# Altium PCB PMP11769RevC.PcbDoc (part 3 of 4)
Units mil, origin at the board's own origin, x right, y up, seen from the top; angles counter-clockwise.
Board outline 7800 x 8510 mil, 4 copper layers (Top, Inner Top, Inner Bottom, Bottom), stack 33.235 mil thick; 451 components, 226 nets, 1199 pads, 1742 vias.
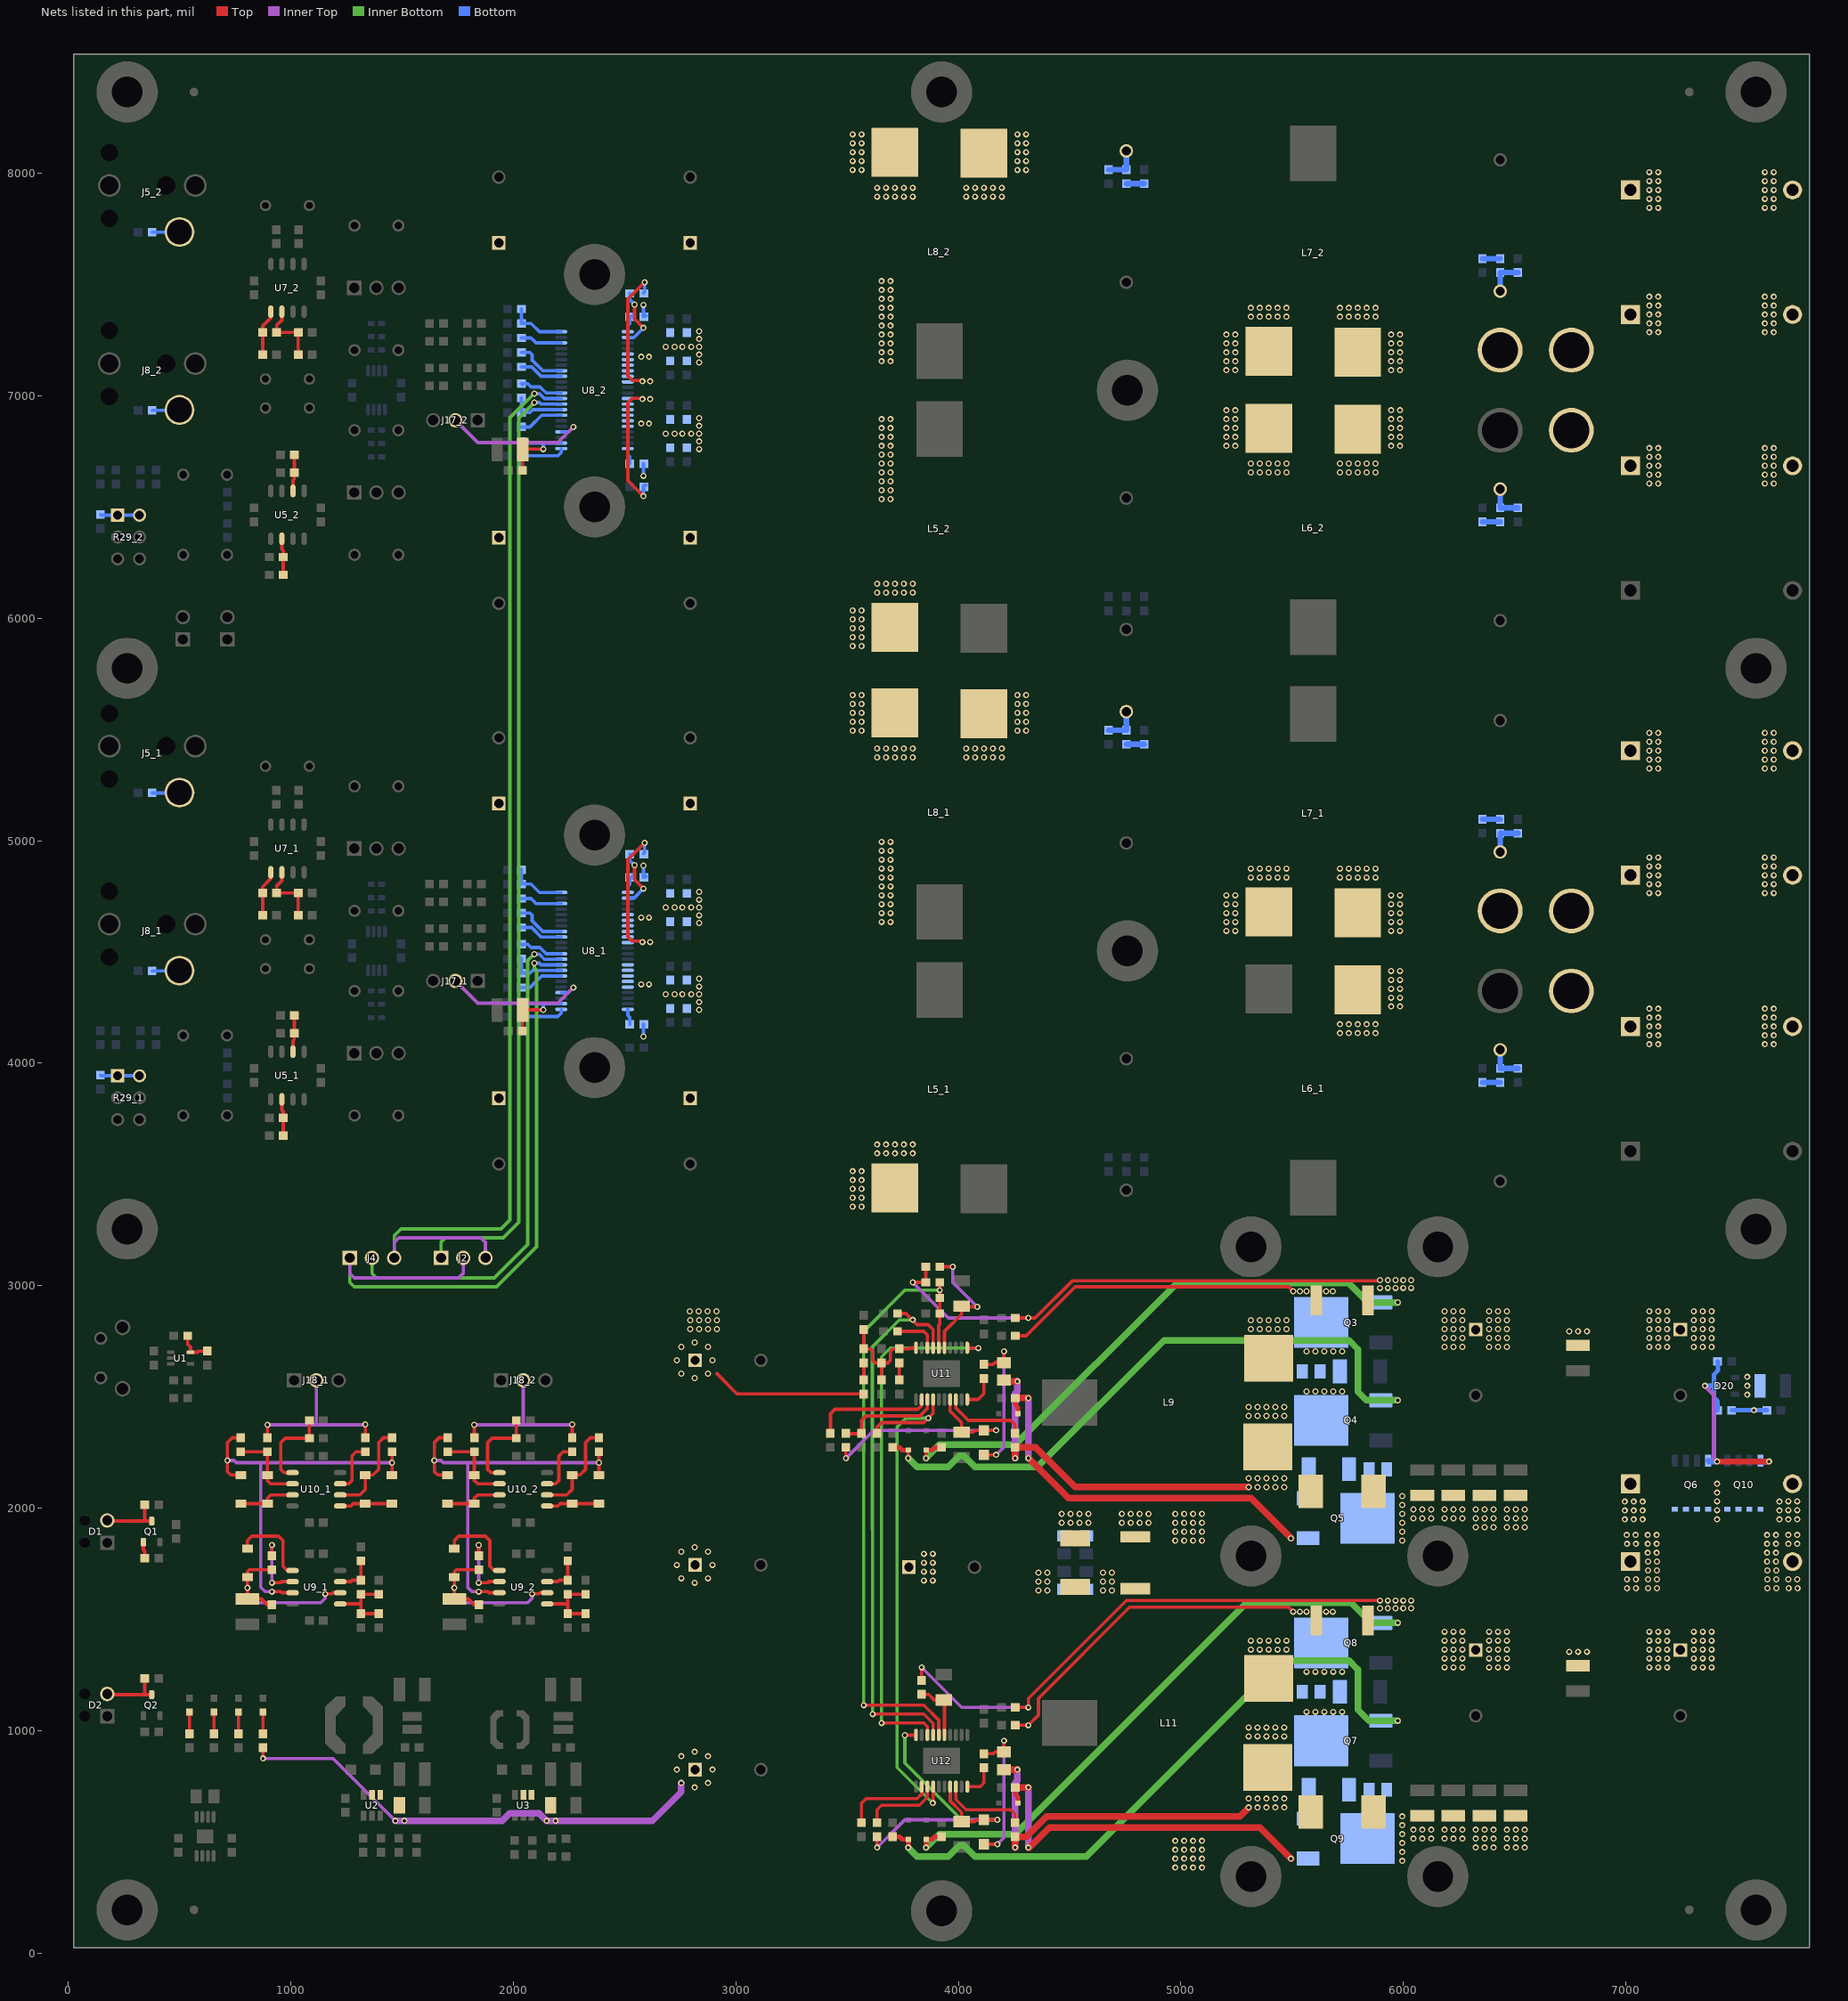
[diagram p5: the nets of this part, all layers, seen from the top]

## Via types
v1: diameter 28, hole 15, Top to Bottom, 1742 vias

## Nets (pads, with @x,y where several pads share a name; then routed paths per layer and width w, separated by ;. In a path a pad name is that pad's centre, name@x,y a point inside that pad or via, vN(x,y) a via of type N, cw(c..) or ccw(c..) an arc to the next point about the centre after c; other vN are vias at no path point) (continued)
NetC54_2_2: C54_2.2 L6_2.2 U8_2.35 | length 576.3
  Top w15: v1(2585,6548.7) 2515,6618.7 2515,6968.7 2535,6988.7 v1@2585,6988.7
  Bottom w15: v1(2585,6548.7) 2585,6593.5 C54_2.2@2586.5,6595 ; C54_2.2@2595,6600.2 C54_2.2@2596.5,6598.7
  other v1: 3655,6535 3695,6535 3655,6575 3695,6575 3655,6615 3695,6615 3655,6655 3695,6655 5315,6655 5355,6655 5395,6655 5435,6655 5475,6655 3655,6695 3695,6695 5315,6695 5355,6695 5395,6695 5435,6695 5475,6695 3655,6735 3695,6735 3655,6775 3695,6775 5205,6775 5245,6775 3655,6815 3695,6815 5205,6815 5245,6815 3655,6855 3695,6855 5205,6855 5245,6855 3655,6895 3695,6895 5205,6895 5245,6895 5205,6935 5245,6935 2580,6985 2615,6985
NetC55_1_1: C55_1.1 U8_1.44 | length 71.2
  Bottom w15: U8_1.44@2514.61,4242.5 2514.61,4215.39 2523.5,4206.5 C55_1.1@2523.5,4175
NetC55_1_2: C55_1.2 L5_1.1 U8_1.39 U8_1.40 | length 53.5
  Bottom w15: v1(2585,4120) C55_1.2@2585,4173.5
  other v1: 3525,3355 3565,3355 3525,3395 3565,3395 3525,3435 3565,3435 3525,3475 3565,3475 3525,3515 3565,3515 3635,3595 3675,3595 3715,3595 3755,3595 3795,3595 3635,3635 3675,3635 3715,3635 3755,3635 3795,3635 2575,4355 2610,4355
NetC55_2_1: C55_2.1 U8_2.44 | length 71.2
  Bottom w15: U8_2.44@2514.61,6762.5 2514.61,6735.39 2523.5,6726.5 C55_2.1@2523.5,6695
NetC55_2_2: C55_2.2 L5_2.1 U8_2.39 U8_2.40 | length 53.5
  Bottom w15: v1(2585,6640) C55_2.2@2585,6693.5
  other v1: 3525,5875 3565,5875 3525,5915 3565,5915 3525,5955 3565,5955 3525,5995 3565,5995 3525,6035 3565,6035 3635,6115 3675,6115 3715,6115 3755,6115 3795,6115 3635,6155 3675,6155 3715,6155 3755,6155 3795,6155 2575,6875 2610,6875
NetC58_1_1: C58_1.1 U8_1.11 | length 203.6
  Bottom w15: C58_1.1@2041.5,4530 C58_1.1@2036.5,4535 2065.02,4535 2080.02,4520 2120,4520 2147.5,4492.5 U8_1.11@2215.39,4492.5
NetC58_2_1: C58_2.1 U8_2.11 | length 203.6
  Bottom w15: C58_2.1@2041.5,7050 C58_2.1@2036.5,7055 2065.02,7055 2080.02,7040 2120,7040 2147.5,7012.5 U8_2.11@2215.39,7012.5
NetC59_1_1: C59_1.1 U8_1.14 | length 196.9
  Bottom w15: C59_1.1@2036.5,4610 2082.65,4610 2125.15,4567.5 U8_1.14@2215.39,4567.5 U8_1.14@2215.39,4567.87
NetC59_2_1: C59_2.1 U8_2.14 | length 196.9
  Bottom w15: C59_2.1@2036.5,7130 2082.65,7130 2125.15,7087.5 U8_2.14@2215.39,7087.5 U8_2.14@2215.39,7087.87
NetC60_1_2: C60_1.2 R46_1.1 U8_1.1 | length 271.1
  Bottom w15: R46_1.1@2036.5,4145 C60_1.2@2036.5,4210 C60_1.2@2046.5,4210 ; C60_1.2@2046.5,4213.7 C60_1.2@2046.5,4210 ; U8_1.1@2215.39,4242.5 2215.39,4225.39 2200,4210 C60_1.2@2046.5,4210
NetC60_2_2: C60_2.2 R46_2.1 U8_2.1 | length 271.1
  Bottom w15: R46_2.1@2036.5,6665 C60_2.2@2036.5,6730 C60_2.2@2046.5,6730 ; C60_2.2@2046.5,6733.7 C60_2.2@2046.5,6730 ; U8_2.1@2215.39,6762.5 2215.39,6745.39 2200,6730 C60_2.2@2046.5,6730
NetC61_1_1: C61_1.1 C62_1.1 C63_1.1 J11_1.1 J12_1.1 J12_1.2 L6_1.1 | length 163.8
  Bottom w25: C62_1.1@6435,4060.28 C61_1.1@6435,3976.5 C63_1.1@6515,3976.5
  other v1: 7105,4085 7145,4085 7625,4085 7665,4085 7105,4125 7145,4125 7625,4125 7665,4125 5715,4135 5755,4135 5795,4135 5835,4135 5875,4135 7105,4165 7145,4165 7625,4165 7665,4165 5715,4175 5755,4175 5795,4175 5835,4175 5875,4175 7105,4205 7145,4205 7625,4205 7665,4205 7105,4245 7145,4245 7625,4245 7665,4245 5945,4255 5985,4255 5945,4295 5985,4295 5945,4335 5985,4335 5945,4375 5985,4375 5945,4415 5985,4415
NetC61_1_2: C61_1.2 R47_1.2 | length 80
  Bottom w25: R47_1.2@6355,3913.5 C61_1.2@6435,3913.5
NetC61_2_1: C61_2.1 C62_2.1 C63_2.1 J11_2.1 J12_2.1 J12_2.2 L6_2.1 | length 163.8
  Bottom w25: C62_2.1@6435,6580.28 C61_2.1@6435,6496.5 C63_2.1@6515,6496.5
  other v1: 7105,6605 7145,6605 7625,6605 7665,6605 7105,6645 7145,6645 7625,6645 7665,6645 5715,6655 5755,6655 5795,6655 5835,6655 5875,6655 7105,6685 7145,6685 7625,6685 7665,6685 5715,6695 5755,6695 5795,6695 5835,6695 5875,6695 7105,6725 7145,6725 7625,6725 7665,6725 7105,6765 7145,6765 7625,6765 7665,6765 5945,6775 5985,6775 5945,6815 5985,6815 5945,6855 5985,6855 5945,6895 5985,6895 5945,6935 5985,6935
NetC61_2_2: C61_2.2 R47_2.2 | length 80
  Bottom w25: R47_2.2@6355,6433.5 C61_2.2@6435,6433.5
NetC64_1_1: C64_1.1 L7_1.1 U8_1.32 | length 581.2
  Top w15: v1@2585,4548.7 2535,4548.7 2515,4568.7 2515,4915 v1(2590,4990)
  Bottom w15: C64_1.1@2585,4941.5 2590,4946.5 v1(2590,4990)
  other v1: 2580,4545 2615,4545 5205,4595 5245,4595 3655,4635 3695,4635 5205,4635 5245,4635 3655,4675 3695,4675 5205,4675 5245,4675 3655,4715 3695,4715 5205,4715 5245,4715 3655,4755 3695,4755 5205,4755 5245,4755 3655,4795 3695,4795 3655,4835 3695,4835 5315,4835 5355,4835 5395,4835 5435,4835 5475,4835 3655,4875 3695,4875 5315,4875 5355,4875 5395,4875 5435,4875 5475,4875 3655,4915 3695,4915 3655,4955 3695,4955 3655,4995 3695,4995
NetC64_1_2: C64_1.2 U8_1.24 | length 268.5
  Top w15: v1(2545,4890) 2545,4825 v1(2585,4785)
  Bottom w15: U8_1.24@2514.61,4742.5 2542.5,4742.5 v1(2585,4785) ; C64_1.2@2523.5,4940 2523.5,4911.5 v1(2545,4890)
NetC64_2_1: C64_2.1 L7_2.1 U8_2.32 | length 581.2
  Top w15: v1@2585,7068.7 2535,7068.7 2515,7088.7 2515,7435 v1(2590,7510)
  Bottom w15: C64_2.1@2585,7461.5 2590,7466.5 v1(2590,7510)
  other v1: 2580,7065 2615,7065 5205,7115 5245,7115 3655,7155 3695,7155 5205,7155 5245,7155 3655,7195 3695,7195 5205,7195 5245,7195 3655,7235 3695,7235 5205,7235 5245,7235 3655,7275 3695,7275 5205,7275 5245,7275 3655,7315 3695,7315 3655,7355 3695,7355 5315,7355 5355,7355 5395,7355 5435,7355 5475,7355 3655,7395 3695,7395 5315,7395 5355,7395 5395,7395 5435,7395 5475,7395 3655,7435 3695,7435 3655,7475 3695,7475 3655,7515 3695,7515
NetC64_2_2: C64_2.2 U8_2.24 | length 268.5
  Top w15: v1(2545,7410) 2545,7345 v1(2585,7305)
  Bottom w15: U8_2.24@2514.61,7262.5 2542.5,7262.5 v1(2585,7305) ; C64_2.2@2523.5,7460 2523.5,7431.5 v1(2545,7410)
NetC65_1_1: C65_1.1 L8_1.2 U8_1.27 U8_1.28 | length 56.4
  Bottom w15: v1(2585,4888.7) 2585,4836.5 C65_1.1@2586.5,4835 ; C65_1.1@2595,4840.2 C65_1.1@2596.5,4838.7
  other v1: 2575,4655 2610,4655 3635,5375 3675,5375 3715,5375 3755,5375 3795,5375 3635,5415 3675,5415 3715,5415 3755,5415 3795,5415 3525,5495 3565,5495 3525,5535 3565,5535 3525,5575 3565,5575 3525,5615 3565,5615 3525,5655 3565,5655
NetC65_1_2: C65_1.2 U8_1.23 | length 83.8
  Bottom w15: U8_1.23@2514.61,4767.5 2514.61,4794.61 2523.5,4803.5 C65_1.2@2523.5,4835 ; C65_1.2@2524.61,4829.8 C65_1.2@2533.5,4838.7
NetC65_2_1: C65_2.1 L8_2.2 U8_2.27 U8_2.28 | length 56.4
  Bottom w15: v1(2585,7408.7) 2585,7356.5 C65_2.1@2586.5,7355 ; C65_2.1@2595,7360.2 C65_2.1@2596.5,7358.7
  other v1: 2575,7175 2610,7175 3635,7895 3675,7895 3715,7895 3755,7895 3795,7895 3635,7935 3675,7935 3715,7935 3755,7935 3795,7935 3525,8015 3565,8015 3525,8055 3565,8055 3525,8095 3565,8095 3525,8135 3565,8135 3525,8175 3565,8175
NetC65_2_2: C65_2.2 U8_2.23 | length 83.8
  Bottom w15: U8_2.23@2514.61,7287.5 2514.61,7314.61 2523.5,7323.5 C65_2.2@2523.5,7355 ; C65_2.2@2524.61,7349.8 C65_2.2@2533.5,7358.7
NetC66_1_2: C66_1.2 C67_1.1 R48_1.1 U8_1.2 | length 396.8
  Top w15: R48_1.1@2041.5,4145 2042.09,4145.59 C67_1.1@2042.09,4238.54 2043.54,4240 v1(2135,4240)
  Bottom w15: C66_1.2@2036.5,4275 2066.02,4275 2073.52,4267.5 2135,4267.5 ; v1(2135,4240) 2135,4267.5 ; U8_1.2@2215.39,4267.5 2135,4267.5
NetC66_2_2: C66_2.2 C67_2.1 R48_2.1 U8_2.2 | length 396.8
  Top w15: R48_2.1@2041.5,6665 2042.09,6665.59 C67_2.1@2042.09,6758.54 2043.54,6760 v1(2135,6760)
  Bottom w15: C66_2.2@2036.5,6795 2066.02,6795 2073.52,6787.5 2135,6787.5 ; v1(2135,6760) 2135,6787.5 ; U8_2.2@2215.39,6787.5 2135,6787.5
NetC68_1_1: C68_1.1 C69_1.1 C70_1.1 J13_1.1 J13_1.2 J14_1.1 L7_1.2 | length 163.8
  Bottom w25: C69_1.1@6435,4949.72 C68_1.1@6435,5033.5 C70_1.1@6515,5033.5
  other v1: 5945,4595 5985,4595 5945,4635 5985,4635 5945,4675 5985,4675 5945,4715 5985,4715 5945,4755 5985,4755 7105,4765 7145,4765 7625,4765 7665,4765 7105,4805 7145,4805 7625,4805 7665,4805 5715,4835 5755,4835 5795,4835 5835,4835 5875,4835 7105,4845 7145,4845 7625,4845 7665,4845 5715,4875 5755,4875 5795,4875 5835,4875 5875,4875 7105,4885 7145,4885 7625,4885 7665,4885 7105,4925 7145,4925 7625,4925 7665,4925
NetC68_1_2: C68_1.2 R50_1.2 | length 80
  Bottom w25: R50_1.2@6355,5096.5 C68_1.2@6435,5096.5
NetC68_2_1: C68_2.1 C69_2.1 C70_2.1 J13_2.1 J13_2.2 J14_2.1 L7_2.2 | length 163.8
  Bottom w25: C69_2.1@6435,7469.72 C68_2.1@6435,7553.5 C70_2.1@6515,7553.5
  other v1: 5945,7115 5985,7115 5945,7155 5985,7155 5945,7195 5985,7195 5945,7235 5985,7235 5945,7275 5985,7275 7105,7285 7145,7285 7625,7285 7665,7285 7105,7325 7145,7325 7625,7325 7665,7325 5715,7355 5755,7355 5795,7355 5835,7355 5875,7355 7105,7365 7145,7365 7625,7365 7665,7365 5715,7395 5755,7395 5795,7395 5835,7395 5875,7395 7105,7405 7145,7405 7625,7405 7665,7405 7105,7445 7145,7445 7625,7445 7665,7445
NetC68_2_2: C68_2.2 R50_2.2 | length 80
  Bottom w25: R50_2.2@6355,7616.5 C68_2.2@6435,7616.5
NetC71_1_2: C71_1.2 U8_1.15 | length 227.7
  Bottom w15: C71_1.2@2036.5,4675 2075,4675 2085,4665 2085,4640 2132.5,4592.5 U8_1.15@2215.39,4592.5
NetC71_2_2: C71_2.2 U8_2.15 | length 227.7
  Bottom w15: C71_2.2@2036.5,7195 2075,7195 2085,7185 2085,7160 2132.5,7112.5 U8_2.15@2215.39,7112.5
NetC72_1_2: C72_1.2 R51_1.1 U8_1.22 | length 259.4
  Bottom w15: R51_1.1@2036.5,4870 C72_1.2@2036.5,4805 2080,4805 2117.5,4767.5 U8_1.22@2215.39,4767.5
NetC72_2_2: C72_2.2 R51_2.1 U8_2.22 | length 259.4
  Bottom w15: R51_2.1@2036.5,7390 C72_2.2@2036.5,7325 2080,7325 2117.5,7287.5 U8_2.22@2215.39,7287.5
NetC73_1_1: C73_1.1 U8_1.20 | length 188.2
  Bottom w15: C73_1.1@2036.5,4740 2080,4740 2102.5,4717.5 U8_1.20@2215.39,4717.5
NetC73_2_1: C73_2.1 U8_2.20 | length 188.2
  Bottom w15: C73_2.1@2036.5,7260 2080,7260 2102.5,7237.5 U8_2.20@2215.39,7237.5
NetC74_1_1: C74_1.1 C75_1.1 C76_1.1 J15_1.1 J16_1.1 J16_1.2 L8_1.1 | length 163.8
  Bottom w25: C76_1.1@4675,5496.5 C74_1.1@4755,5496.5 C75_1.1@4755,5580.28
  other v1: 7105,5325 7145,5325 7625,5325 7665,5325 7105,5365 7145,5365 7625,5365 7665,5365 4035,5375 4075,5375 4115,5375 4155,5375 4195,5375 7105,5405 7145,5405 7625,5405 7665,5405 4035,5415 4075,5415 4115,5415 4155,5415 4195,5415 7105,5445 7145,5445 7625,5445 7665,5445 7105,5485 7145,5485 7625,5485 7665,5485 4265,5495 4305,5495 4265,5535 4305,5535 4265,5575 4305,5575 4265,5615 4305,5615 4265,5655 4305,5655
NetC74_1_2: C74_1.2 R52_1.2 | length 80
  Bottom w25: C74_1.2@4755,5433.5 R52_1.2@4835,5433.5
NetC74_2_1: C74_2.1 C75_2.1 C76_2.1 J15_2.1 J16_2.1 J16_2.2 L8_2.1 | length 163.8
  Bottom w25: C76_2.1@4675,8016.5 C74_2.1@4755,8016.5 C75_2.1@4755,8100.28
  other v1: 7105,7845 7145,7845 7625,7845 7665,7845 7105,7885 7145,7885 7625,7885 7665,7885 4035,7895 4075,7895 4115,7895 4155,7895 4195,7895 7105,7925 7145,7925 7625,7925 7665,7925 4035,7935 4075,7935 4115,7935 4155,7935 4195,7935 7105,7965 7145,7965 7625,7965 7665,7965 7105,8005 7145,8005 7625,8005 7665,8005 4265,8015 4305,8015 4265,8055 4305,8055 4265,8095 4305,8095 4265,8135 4305,8135 4265,8175 4305,8175
NetC74_2_2: C74_2.2 R52_2.2 | length 80
  Bottom w25: C74_2.2@4755,7953.5 R52_2.2@4835,7953.5
NetC79_1_1: C79_1.1 D11_1.1 R56_1.1 R60_1.2 U9_1.6 | length 862.5
  Top w15: R60_1.2@915,1566.5 893.5,1566.5 867.91,1592.09 C79_1.1@805,1592.09 v1(805,1642.22) D11_1.1@805,1690.53 805,1715 813.5,1723.5 R56_1.1@915,1723.5 ; v1(1155,1615) 1185,1615 1190,1620 U9_1.6@1222.28,1620
  Inner Top w15: v1(805,1642.22) 805,1595 825,1575 1135,1575 1155,1595 v1(1155,1615) v1@1153.33,1616.67
NetC79_2_1: C79_2.1 D11_2.1 R56_2.1 R60_2.2 U9_2.6 | length 862.5
  Top w15: R60_2.2@1845,1566.5 1823.5,1566.5 1797.91,1592.09 C79_2.1@1735,1592.09 v1(1735,1642.22) D11_2.1@1735,1690.53 1735,1715 1743.5,1723.5 R56_2.1@1845,1723.5 ; v1(2085,1615) 2115,1615 2120,1620 U9_2.6@2152.28,1620
  Inner Top w15: v1(1735,1642.22) 1735,1595 1755,1575 2065,1575 2085,1595 v1(2085,1615) v1@2083.33,1616.67
NetC81_1_2: C81_1.2 R57_1.1 R61_1.1 R62_1.1 U9_1.5 | length 339.7
  Top w15: U9_1.5@1222.28,1570 1315,1570 ; C81_1.2@1395,1526.5 R61_1.1@1315,1526.5 1315,1570 ; R57_1.1@1395,1613.5 R62_1.1@1315,1613.5 1315,1570
NetC81_2_2: C81_2.2 R57_2.1 R61_2.1 R62_2.1 U9_2.5 | length 339.7
  Top w15: U9_2.5@2152.28,1570 2245,1570 ; C81_2.2@2325,1526.5 R61_2.1@2245,1526.5 2245,1570 ; R57_2.1@2325,1613.5 R62_2.1@2245,1613.5 2245,1570
NetC85_2: C85.2 R74.1 | length 77
  Top w15: C85.2@3735,2576.5 R74.1@3735,2653.5
NetC88_1: C88.1 D14.1 R72.1 | length 683.1
  Top w15: D14.1@4115,2239.88 4115.12,2240 v1(4170,2240) ; R72.1@4115,2646.5 4156.5,2646.5 4165,2655 C88.1@4205,2655 v1(4205,2705)
  Inner Top w15: v1(4170,2240) 4205,2275 v1@4205,2710
NetC89_1: C89.1 D15.1 R73.1 | length 681.3
  Top w15: D15.1@4115,489.88 4115.12,490 v1(4175,490) ; R73.1@4115,896.5 4156.5,896.5 4165,905 C89.1@4205,905 v1(4205,955)
  Inner Top w15: v1(4175,490) 4205.37,520.37 4205.37,954.63 v1(4205,955)
NetC90_2: C90.2 R74.2 R78.1 R85.2 R86.2 U11.10 | length 490.3
  Top w15: R86.2@3575,2803.5 R78.1@3575,2716.5 3603.5,2716.5 3615,2705 3615,2665 3626.5,2653.5 R85.2@3655,2653.5 ; C90.2@3655,2576.5 R85.2@3655,2653.5 ; 3778.5,2716.5 3706.5,2716.5 3695,2705 3695,2665 3683.5,2653.5 R85.2@3655,2653.5 ; 3786.14,2721.14 U11.10@3809.84,2721.14
NetC92_2: C92.2 R69.1 U11.5 | length 574.3
  Top w15: R69.1@3916.5,3085 v1(3975,3085) ; U11.5@3937.8,2721.14 3937.8,2794.65 3937.48,2794.96 4015,2872.48 C92.2@4015,2907.91 4017.91,2905 v1(4085,2905)
  Inner Top w15: v1(3975,3085) 3975,3015 v1(4085,2905)
NetC93_2: C93.2 R71.1 U12.5 | length 258.5
  Top w15: R71.1@3835,1163.5 3866.5,1163.5 3892.09,1137.91 C93.2@3935,1137.91 ; C93.2@3935,1127.91 3937.8,1125.12 U12.5@3937.8,981.14
NetC95_1: C95.1 R87.2
NetC95_2: C95.2 C99.1 C100.1 C102.1 C103.1 C107.2 C111.2 C115.2 C119.1 C120.1 C122.1 C123.1 D16.1 D21.1 L10.1 Q5.4 Q9.4 R96.1
  other v1: 4975,385 5015,385 5055,385 5095,385 5995,415 4975,425 5015,425 5055,425 5095,425 5995,455 4975,465 5015,465 5055,465 5095,465 6325,475 6365,475 6405,475 6465,475 6505,475 6545,475 5995,495 4975,505 5015,505 5055,505 5095,505 6045,515 6085,515 6125,515 6185,515 6225,515 6265,515 6325,515 6365,515 6405,515 6465,515 6505,515 6545,515 5995,535 6045,555 6085,555 6125,555 6185,555 6225,555 6265,555 6325,555 6365,555 6405,555 6465,555 6505,555 6545,555 5995,575 5995,615 4975,1855 5015,1855 5055,1855 5095,1855 5995,1855 4975,1895 5015,1895 5055,1895 5095,1895 5995,1895 6325,1915 6365,1915 6405,1915 6465,1915 6505,1915 6545,1915 4465,1935 4505,1935 4545,1935 4585,1935 4735,1935 4775,1935 4815,1935 4855,1935 4975,1935 5015,1935 5055,1935 5095,1935 5995,1935 6045,1955 6085,1955 6125,1955 6185,1955 6225,1955 6265,1955 6325,1955 6365,1955 6405,1955 6465,1955 6505,1955 6545,1955 4465,1975 4505,1975 4545,1975 4585,1975 4735,1975 4775,1975 4815,1975 4855,1975 4975,1975 5015,1975 5055,1975 5095,1975 5995,1975 6045,1995 6085,1995 6125,1995 6185,1995 6225,1995 6265,1995 6325,1995 6365,1995 6405,1995 6465,1995 6505,1995 6545,1995 5995,2015 5995,2055
NetC96_2: C96.2 R90.2
NetC106_2: C106.2 D20.3 Q6.4 Q10.4 R89.2 | length 958.2
  Top w25: v1(7410,2210) v1(7643.5,2210)
  Inner Top w20: v1(7355,2550) 7395,2510 7395,2225 v1(7410,2210)
  Bottom w20: v1(7355,2550) D20.3@7396.26,2550 ; R89.2@7410,2438 R89.2@7412,2440 7412,2481.5 7396.26,2497.24 D20.3@7396.26,2550 ; C106.2@7412,2660 7413.5,2658.5 7413.5,2618.9 7396.26,2601.65 D20.3@7396.26,2550
  Bottom w25: Q6.4@7370,2214.3 7374.3,2210 v1(7410,2210) ; Q10.4@7603.5,2214.3 7607.8,2210 v1(7643.5,2210)
NetC111_1: C111.1 R97.2
NetC116_2: C116.2 R99.2
NetD1_2: D1.2 Q1.3 R2.1 | length 274.4
  Top w15: D1.2@175.2,1945.2 178.15,1942.24 345,1942.24 ; R2.1@343.5,2015 343.5,1943.74 345,1942.24 ; Q1.3@375,1942.24 345,1942.24
NetD2_2: D2.2 Q2.3 R8.1 | length 274.4
  Top w15: D2.2@175.2,1165.2 178.15,1162.24 345,1162.24 ; R8.1@343.5,1235 343.5,1163.74 345,1162.24 ; Q2.3@375,1162.24 345,1162.24
NetD4_2: D4.2 R12.1 | length 97
  Top w15: R12.1@875,986.5 D4.2@875,1083.5
NetD5_2: D5.2 R13.1 | length 97
  Top w15: R13.1@765,986.5 D5.2@765,1083.5
NetD6_1: D6.1 R14.1 | length 97
  Top w15: R14.1@655,986.5 D6.1@655,1083.5
NetD7_2: D7.2 R15.1 | length 97
  Top w15: R15.1@545,986.5 D7.2@545,1083.5
NetD9_1_1: D9_1.1 D10_1.2 U10_1.1 | length 237.1
  Top w15: U10_1.1@1222.28,2010 1270,2010 1280.53,2020.53 D9_1.1@1335,2020.53 D10_1.2@1455,2020.53
NetD9_1_2: D9_1.2 R55_1.2 U10_1.2 | length 447
  Top w15: U10_1.2@1222.28,2060 1309.99,2060 1335,2085.01 D9_1.2@1335,2149.47 1369.47,2149.47 1395,2175 1395,2295 1416.5,2316.5 R55_1.2@1455,2316.5
NetD9_2_1: D9_2.1 D10_2.2 U10_2.1 | length 237.1
  Top w15: U10_2.1@2152.28,2010 2200,2010 2210.53,2020.53 D9_2.1@2265,2020.53 D10_2.2@2385,2020.53
NetD9_2_2: D9_2.2 R55_2.2 U10_2.2 | length 447
  Top w15: U10_2.2@2152.28,2060 2239.99,2060 2265,2085.01 D9_2.2@2265,2149.47 2299.47,2149.47 2325,2175 2325,2295 2346.5,2316.5 R55_2.2@2385,2316.5
NetD10_1_1: D10_1.1 D13_1.1 R55_1.1 R63_1.1 U9_1.3 | length 1826.5
  Top w15: D13_1.1@775,2149.47 730.53,2149.47 715,2165 v1(715,2215) 715,2295 736.5,2316.5 R63_1.1@775,2316.5 ; v1(915,1625) 955,1625 960,1620 U9_1.3@1007.72,1620 ; D10_1.1@1455,2149.47 v1(1455,2205) R55_1.1@1455,2253.5
  Inner Top w15: v1(715,2215) 745,2215 755.37,2204.63 865,2204.63 ; v1(915,1625) 885,1625 865,1645 865,2204.63 ; v1(1455,2205) 1454.63,2204.63 865,2204.63
NetD10_2_1: D10_2.1 D13_2.1 R55_2.1 R63_2.1 U9_2.3 | length 1826.5
  Top w15: D13_2.1@1705,2149.47 1660.53,2149.47 1645,2165 v1(1645,2215) 1645,2295 1666.5,2316.5 R63_2.1@1705,2316.5 ; v1(1845,1625) 1885,1625 1890,1620 U9_2.3@1937.72,1620 ; D10_2.1@2385,2149.47 v1(2385,2205) R55_2.1@2385,2253.5
  Inner Top w15: v1(1645,2215) 1675,2215 1685.37,2204.63 1795,2204.63 ; v1(1845,1625) 1815,1625 1795,1645 1795,2204.63 ; v1(2385,2205) 2384.63,2204.63 1795,2204.63
NetD11_1_2: D11_1.2 U9_1.1 | length 378.5
  Top w15: D11_1.2@805,1819.47 805,1855 825,1875 945,1875 965,1855 965,1739.33 984.33,1720 U9_1.1@1007.72,1720
NetD11_2_2: D11_2.2 U9_2.1 | length 378.5
  Top w15: D11_2.2@1735,1819.47 1735,1855 1755,1875 1875,1875 1895,1855 1895,1739.33 1914.33,1720 U9_2.1@1937.72,1720
NetD12_1_1: D12_1.1 D13_1.2 U10_1.7 | length 263.4
  Top w15: D13_1.2@775,2020.53 D12_1.1@895,2020.53 895,2045 910,2060 U10_1.7@1007.72,2060
NetD12_1_2: D12_1.2 R63_1.2 R64_1.2 U10_1.6 | length 367.4
  Top w15: R63_1.2@775,2253.5 R64_1.2@895,2253.5 D12_1.2@895,2149.46 895,2125 910,2110 U10_1.6@1007.72,2110
NetD12_2_1: D12_2.1 D13_2.2 U10_2.7 | length 263.4
  Top w15: D13_2.2@1705,2020.53 D12_2.1@1825,2020.53 1825,2045 1840,2060 U10_2.7@1937.72,2060
NetD12_2_2: D12_2.2 R63_2.2 R64_2.2 U10_2.6 | length 367.4
  Top w15: R63_2.2@1705,2253.5 R64_2.2@1825,2253.5 D12_2.2@1825,2149.46 1825,2125 1840,2110 U10_2.6@1937.72,2110
NetD17_2: D17.2 Q3.1 R93.2 | length 2594.3
  Top w15: v1(3855,2225) D17.2@3855,2261.69
  Top w20: D17.2@3855,2261.69 3882.19,2261.69 3894,2273.5 R93.2@3925,2273.5
  Inner Bottom w30: v1(3855,2225) 3915,2285 4255,2285 4982.87,3012.87 5753.9,3012.87 5841.77,2925 v1(5975,2925)
NetD18_2: D18.2 Q4.1 R94.2 | length 2829.3
  Top w15: v1(3775,2225) D18.2@3775,2261.69
  Top w20: R94.2@3705,2273.5 3736,2273.5 3747.81,2261.69 D18.2@3775,2261.69
  Inner Bottom w30: v1(3775,2225) 3815,2185 3955,2185 4005,2235 4025,2235 4075,2185 4355,2185 4925,2755 5755,2755 5795,2715 5795,2524.13 5834.13,2485 v1(5975,2485)
NetD19_2: D19.2 Q5.1 R95.2 | length 1712.5
  Top w20: R95.2@4256.5,2495 4256.5,2464 4268.31,2452.19 D19.2@4268.31,2425
  Top w30: R95.2@4256.5,2495 v1(4315,2495) ; v1(4315,2225) 4495,2045 5315,2045 v1(5495,1865)
  Inner Top w30: v1@4315,2235 v1@4315,2485
NetD22_2: D22.2 Q7.1 R102.2 | length 2951.4
  Top w20: R102.2@3705,523.5 3736,523.5 3747.81,511.69 D22.2@3775,511.69 v1(3775,475)
  Inner Bottom w30: v1(3775,475) 3815,435 3955,435 4005,485 4025,485 4075,435 4575,435 5455,1315 5755,1315 5795,1275 5795,1095 5845,1045 v1(5975,1045)
NetD23_2: D23.2 Q8.1 R103.2 | length 2724.5
  Top w20: v1(3855,475) D23.2@3855,511.69 3882.19,511.69 3894,523.5 R103.2@3925,523.5
  Inner Bottom w30: v1(3855,475) 3915,535 4255,535 5295,1575 5765,1575 5855,1485 v1(5975,1485)
NetD24_2: D24.2 Q9.1 R104.2 | length 1678.7
  Top w20: R104.2@4256.5,745 4256.5,714 4268.31,702.19 D24.2@4268.31,675
  Top w30: R104.2@4256.5,745 v1(4315,745) ; v1(4315,475) 4318.56,475 4408.56,565 5355,565 v1(5495,425)
  Inner Top w30: v1(4315,475) v1(4315,745)
NetJ5_1_4: J5_1.4 R23_1.2 | length 124
  Bottom w15: R23_1.2@376.5,5215 498.62,5215 J5_1.4@499.96,5216.34
NetJ5_2_4: J5_2.4 R23_2.2 | length 124
  Bottom w15: R23_2.2@376.5,7735 498.62,7735 J5_2.4@499.96,7736.34
NetJ8_1_4: J8_1.4 R40_1.2 | length 124
  Bottom w15: R40_1.2@376.5,4415 498.62,4415 J8_1.4@499.96,4416.34
NetJ8_2_4: J8_2.4 R40_2.2 | length 124
  Bottom w15: R40_2.2@376.5,6935 498.62,6935 J8_2.4@499.96,6936.34
NetJ17_1_2: J17_1.2 U8_1.4 | length 664.3
  Inner Top w15: J17_1.2@1740,4370 1840,4270 2200,4270 v1(2270,4340)
  Bottom w15: U8_1.4@2215.39,4317.5 2247.5,4317.5 v1(2270,4340)
NetJ17_2_2: J17_2.2 U8_2.4 | length 664.3
  Inner Top w15: J17_2.2@1740,6890 1840,6790 2200,6790 v1(2270,6860)
  Bottom w15: U8_2.4@2215.39,6837.5 2247.5,6837.5 v1(2270,6860)
NetJ18_1_2: J18_1.2 R59_1.1 R64_1.1 | length 759.1
  Top w15: R64_1.1@895,2316.5 v1(895,2375) ; R59_1.1@1335,2316.5 v1(1335,2376.5)
  Inner Top w15: v1(895,2375) 1115,2375 ; J18_1.2@1115,2575 1115,2375 ; v1(1335,2376.5) 1333.5,2375 1115,2375
NetJ18_2_2: J18_2.2 R59_2.1 R64_2.1 | length 759.1
  Top w15: R64_2.1@1825,2316.5 v1(1825,2375) ; R59_2.1@2265,2316.5 v1(2265,2376.5)
  Inner Top w15: v1(1825,2375) 2045,2375 ; J18_2.2@2045,2575 2045,2375 ; v1(2265,2376.5) 2263.5,2375 2045,2375
NetJ20_1: J20.1 J20.2 Q6.5 Q6.6 Q6.7 Q6.8 Q10.5 Q10.6 Q10.7 Q10.8
  other v1: 6995,1950 7035,1950 7075,1950 7410,1950 7690,1950 7730,1950 7770,1950 6995,1990 7035,1990 7075,1990 7690,1990 7410,1991.5 7730,1991.5 7770,1991.5 6995,2030 7035,2030 7075,2030 7690,2030 7410,2031.5 7730,2031.5 7770,2031.5 7410,2070 7410,2110
NetL9_2: L9.2 R88.2 R92.2 | length 1347.9
  Top w15: R92.2@4256.5,2775 4305,2775 4525,2995 5485,2995 v1(5505,2975)
  other v1: 5315,2805 5355,2805 5395,2805 5435,2805 5475,2805 5315,2845 5355,2845 5395,2845 5435,2845 5475,2845 5535,2975 5565,2975 5653,2975 5683,2975
NetL11_2: L11.2 R98.2 R101.2 | length 1510.5
  Top w15: R101.2@4256.5,1025 v1@4305,1025 ; v1(4315,1025) 4359.82,1069.82 4359.82,1145.31 4769.52,1555 5485,1555 v1(5505,1535)
  other v1: 5315,1365 5355,1365 5395,1365 5435,1365 5475,1365 5315,1405 5355,1405 5395,1405 5435,1405 5475,1405 5535,1535 5565,1535 5653,1535 5683,1535
NetQ1_1: Q1.1 R4.2 | length 75.2
  Top w15: Q1.1@337.6,1847.76 337.6,1812.4 343.5,1806.5 R4.2@343.5,1775
NetR5_1: R5.1 R6.2 U1.5 | length 157.9
  Top w15: R6.2@536.5,2775 536.5,2736.65 549.29,2723.86 U1.5@549.29,2700.59 580.59,2700.59 586.5,2706.5 R5.1@625,2706.5
NetR25_1_1: R25_1.1 R28_1.2 R33_1.2 U7_1.2 | length 299.5
  Top w15: U7_1.2@960,4857.72 960,4820 936.5,4796.5 R25_1.1@936.5,4765 R33_1.2@1033.5,4765 R28_1.2@1033.5,4665
NetR25_1_2: R25_1.2 R35_1.1 U7_1.1 | length 207.8
  Top w15: R35_1.1@873.5,4665 R25_1.2@873.5,4765 873.5,4793.5 910,4830 U7_1.1@910,4857.72
NetR25_2_1: R25_2.1 R28_2.2 R33_2.2 U7_2.2 | length 299.5
  Top w15: U7_2.2@960,7377.72 960,7340 936.5,7316.5 R25_2.1@936.5,7285 R33_2.2@1033.5,7285 R28_2.2@1033.5,7185
NetR25_2_2: R25_2.2 R35_2.1 U7_2.1 | length 207.8
  Top w15: R35_2.1@873.5,7185 R25_2.2@873.5,7285 873.5,7313.5 910,7350 U7_2.1@910,7377.72
NetR29_1_1: R29_1.1 R29_1.1' R32_1.2 | length 176.5
  Bottom w15: R32_1.2@145,3946.5 148.07,3943.43 R29_1.1@221.85,3943.43 R29_1.1'@320.28,3943.43
NetR29_2_1: R29_2.1 R29_2.1' R32_2.2 | length 176.5
  Bottom w15: R32_2.2@145,6466.5 148.07,6463.43 R29_2.1@221.85,6463.43 R29_2.1'@320.28,6463.43
NetR30_1_1: R30_1.1 R31_1.1 U5_1.2 | length 165.4
  Top w15: U5_1.2@960,3837.72 960,3790 966.5,3783.5 R31_1.1@966.5,3755 R30_1.1@966.5,3675
NetR30_2_1: R30_2.1 R31_2.1 U5_2.2 | length 165.4
  Top w15: U5_2.2@960,6357.72 960,6310 966.5,6303.5 R31_2.1@966.5,6275 R30_2.1@966.5,6195
NetR43_1_1: R43_1.1 R44_1.1 U5_1.6 | length 165.4
  Top w15: U5_1.6@1010,4052.28 1010,4100 1015,4105 1015,4133.5 R44_1.1@1016.5,4135 R43_1.1@1016.5,4215
NetR43_2_1: R43_2.1 R44_2.1 U5_2.6 | length 165.4
  Top w15: U5_2.6@1010,6572.28 1010,6620 1015,6625 1015,6653.5 R44_2.1@1016.5,6655 R43_2.1@1016.5,6735
NetR49_1_2: R49_1.2 U8_1.7 | length 200.6
  Bottom w15: R49_1.2@2036.5,4340 2075,4340 2127.5,4392.5 U8_1.7@2215.39,4392.5
NetR49_2_2: R49_2.2 U8_2.7 | length 200.6
  Bottom w15: R49_2.2@2036.5,6860 2075,6860 2127.5,6912.5 U8_2.7@2215.39,6912.5
NetR53_1_2: R53_1.2 R54_1.2 U8_1.8 | length 249.1
  Bottom w15: R54_1.2@2036.5,4470 R53_1.2@2036.5,4405 2075,4405 2087.5,4417.5 U8_1.8@2215.39,4417.5
NetR53_2_2: R53_2.2 R54_2.2 U8_2.8 | length 249.1
  Bottom w15: R54_2.2@2036.5,6990 R53_2.2@2036.5,6925 2075,6925 2087.5,6937.5 U8_2.8@2215.39,6937.5
NetR56_1_2: R56_1.2 U9_1.2 | length 313.3
  Top w15: v1(915,1665) 955,1665 960,1670 U9_1.2@1007.72,1670 ; R56_1.2@915,1786.5 v1(915,1835)
  Inner Top w15: v1(915,1665) v1(915,1835)
NetR56_2_2: R56_2.2 U9_2.2 | length 313.3
  Top w15: v1(1845,1665) 1885,1665 1890,1670 U9_2.2@1937.72,1670 ; R56_2.2@1845,1786.5 v1(1845,1835)
  Inner Top w15: v1(1845,1665) v1(1845,1835)
NetR58_1_1: R58_1.1 R62_1.2 U9_1.7 | length 182.4
  Top w15: U9_1.7@1222.28,1670 1270,1670 1276.5,1676.5 R62_1.2@1315,1676.5 R58_1.1@1315,1763.5
NetR58_2_1: R58_2.1 R62_2.2 U9_2.7 | length 182.4
  Top w15: U9_2.7@2152.28,1670 2200,1670 2206.5,1676.5 R62_2.2@2245,1676.5 R58_2.1@2245,1763.5
NetR59_1_2: R59_1.2 U10_1.3 | length 236.6
  Top w15: U10_1.3@1222.28,2110 1260,2110 1275,2125 1275,2235 1293.5,2253.5 R59_1.2@1335,2253.5
NetR59_2_2: R59_2.2 U10_2.3 | length 236.6
  Top w15: U10_2.3@2152.28,2110 2190,2110 2205,2125 2205,2235 2223.5,2253.5 R59_2.2@2265,2253.5
NetR65_1_2: R65_1.2 R66_1.2 U10_1.5 | length 395.7
  Top w15: U10_1.5@1007.72,2160 970,2160 955,2175 955,2295 975,2315 R65_1.2@1083.5,2315 R66_1.2@1083.5,2395
NetR65_2_2: R65_2.2 R66_2.2 U10_2.5 | length 395.7
  Top w15: U10_2.5@1937.72,2160 1900,2160 1885,2175 1885,2295 1905,2315 R65_2.2@2013.5,2315 R66_2.2@2013.5,2395
NetR67_2: R67.2 R79.1 U11.13 | length 496.2
  Top w15: R67.2@3495,2335 3565,2335 3565,2393.5 ; 3565,2395 3585,2415 3827.35,2415 3860.71,2448.36 U11.13@3860.71,2498.23
NetR70_2: R70.2 U12.13 | length 355.6
  Top w15: R70.2@3635,585 3635,643.5 ; 3635,645 3655,665 3825,665 3861.02,701.02 U12.13@3861.02,748.86
NetR72_2: R72.2 U11.20 | length 154.2
  Top w15: U11.20@4040.16,2488.86 4088.86,2488.86 4115,2515 R72.2@4115,2583.5
NetR73_2: R73.2 U12.20 | length 150
  Top w15: U12.20@4040.16,748.86 4098.86,748.86 4115,765 R73.2@4115,833.5
NetR75_2: R75.2 U11.18 | length 383.4
  Top w15: U11.18@3988.66,2498.23 3988.66,2451.34 4045,2395 4235,2395 4255,2375 R75.2@4255,2336.5
NetR76_2: R76.2 U12.18 | length 389.7
  Top w15: U12.18@3988.98,748.86 3988.98,691.02 4035,645 4235,645 4255,625 R76.2@4255,586.5
NetR77_2: R77.2 R78.2 | length 77
  Top w15: R77.2@3575,2576.5 R78.2@3575,2653.5
NetR81_2: R81.2 U11.12 | length 541.4
  Top w15: R81.2@3425,2336.5 3425,2425 3445,2445 3818.95,2445 3834.07,2460.12 3834.07,2487.5 U11.12@3835.43,2488.86
NetR82_2: R82.2 U11.8 | length 199
  Top w15: R82.2@3726.5,2795 3845,2795 3861.02,2778.98 U11.8@3861.02,2721.14
NetR84_2: R84.2 U12.12 | length 409.1
  Top w15: R84.2@3565,586.5 3565,675 3585,695 3815,695 3835.43,715.43 U12.12@3835.43,748.86
OSC_IOM1: J2.2 J4.1 U8_1.9 | length 3107.1
  Inner Top w15: J4.1@1265,3125 1265,3055 1285,3035 1755,3035 1775,3055 J2.2@1775,3125
  Inner Bottom w15: J4.1@1265,3125 1265,3015 1285,2995 1925,2995 2105,3175 2105,4417.5 2095,4427.5 v1(2095,4450) v1@2095,4455
  Bottom w15: v1(2095,4450) 2117.3,4450 2124.8,4442.5 U8_1.9@2215.39,4442.5
OSC_IOM2: J2.1 U8_2.9 | length 4294.8
  Inner Bottom w15: J2.1@1675,3125 1675,3195 1695,3215 1955,3215 2025,3285 2025,6900 v1(2095,6970)
  Bottom w15: v1(2095,6970) 2117.3,6970 2124.8,6962.5 U8_2.9@2215.39,6962.5
OSC_IOP1: J4.2 U8_1.10 | length 2288.5
  Inner Bottom w15: J4.2@1365,3125 1365,3055 1385,3035 1915,3035 2065,3185 2065,4461.54 2093.46,4490 v1(2095,4490)
  Bottom w15: v1(2095,4490) 2117.3,4490 2139.8,4467.5 U8_1.10@2215.39,4467.5
OSC_IOP2: J2.3 J4.3 U8_2.10 | length 5106.7
  Inner Top w15: J4.3@1465,3125 1465,3195 1485,3215 1855,3215 1875,3195 J2.3@1875,3125
  Inner Bottom w15: J4.3@1465,3125 1465,3225 1495,3255 1945,3255 1985,3295 1985,6901.54 2093.46,7010 v1(2095,7010)
  Bottom w15: v1(2095,7010) 2117.3,7010 2139.8,6987.5 U8_2.10@2215.39,6987.5
PVDD: C4.1 C13.1 C42_1.1 C42_2.1 C43_1.1 C43_2.1 C44_1.1 C44_2.1 C45_1.1 C45_2.1 C46_1.1 C46_2.1 C47_1.1 C47_2.1 C48_1.1 C48_2.1 C49_1.1 C49_2.1 C50_1.1 C50_2.1 C51_1.1 C51_2.1 C52_1.1 C52_2.1 C53_1.1 C53_2.1 C108.1 C109.1 C110.1 C112.1 C113.1 C114.1 L10.2 R12.2 R77.1 R96.2 U2.4 U2.5 U3.4 U3.5 U8_1.29 U8_1.30 U8_1.31 U8_1.36 U8_1.37 U8_1.38 U8_2.29 U8_2.30 U8_2.31 U8_2.36 U8_2.37 U8_2.38 | length 2864.9
  Top w15: v1(875,875) R12.2@875,923.5 ; 2915,2605 3006.5,2513.5 R77.1@3575,2513.5
  Inner Top w15: v1(875,875) 1190,875 v1(1470,595)
  Inner Top w30: v1(1470,595) v1(1510,595) 1949.41,595 1983.98,629.57 2115.43,629.57 v1(2150,595) v1(2190,595) 2625,595 2755,725 v1(2755,765)
  other v1: 2815,745 2875,765 2735,825 2895,825 2755,885 2875,885 2815,905 4360,1630 4400,1630 4650,1630 4690,1630 2815,1665 4360,1670 4400,1670 4650,1670 4690,1670 3845,1675 3885,1675 2755,1685 2875,1685 4360,1710 4400,1710 4650,1710 4690,1710 3845,1715 3885,1715 2735,1745 2895,1745 3845,1755 3885,1755 3845,1795 3885,1795 2755,1805 2875,1805 2815,1825 2815,2585 2755,2605 2875,2605 2735,2665 2895,2665 2755,2725 2875,2725 2815,2745 2795,2805 2835,2805 2875,2805 2915,2805 2795,2845 2835,2845 2875,2845 2915,2845 2793.5,2885 2833.5,2885 2873.5,2885 2913.5,2885 2835,4240 2835,4275 2685,4310 2725,4310 2760,4310 2800,4310 2835,4310 2835,4345 2835,4380 2835,4630 2835,4665 2685,4700 2725,4700 2760,4700 2800,4700 2835,4700 2835,4735 2835,4770 2835,6760 2835,6795 2685,6830 2725,6830 2760,6830 2800,6830 2835,6830 2835,6865 2835,6900 2835,7150 2835,7185 2685,7220 2725,7220 2760,7220 2800,7220 2835,7220 2835,7255 2835,7290
RES: R83.2 U11.14 U12.14 | length 2355.3
  Top w15: R83.2@3635,2335 3635,2363.5 ; 3635,2365 3655,2385 3845,2385 v1(3865,2405) 3886.61,2426.61 U11.14@3886.61,2488.86 ; v1(3885,675) 3886.61,676.61 U12.14@3886.61,748.86
  Inner Bottom w15: v1(3865,2405) 3765,2405 3725,2365 3725,835 v1(3885,675)
SS: C94.1 U11.7 U12.7 | length 2496.7
  Top w15: v1(3615,1075) 3845,1075 3886.61,1033.39 U12.7@3886.61,981.14 U12.7@3885.26,982.5 ; C94.1@3726.5,2875 3765,2875 3815,2825 3865,2825 3886.61,2803.39 U11.7@3886.61,2721.14
  Inner Bottom w15: v1(3615,1075) 3613.54,2725 3734.84,2846.3 v1(3795,2846.3)
SW-1: C88.2 C96.1 D16.2 L9.1 Q3.4 Q4.4 Q5.3 R75.1 R87.1 | length 1583.7
  Top w30: C88.2@4205,2575 4210,2570 v1(4265,2570) ; v1(4255,2225) R75.1@4255,2273.5 4346.5,2273.5 4525,2095 v1(5305,2095)
  Inner Top w30: v1(4255,2225) 4255,2515 4265,2525 v1(4265,2570)
  other v1: 5345,2095 5385,2095 5425,2095 5465,2095 5305,2135 5345,2135 5385,2135 5425,2135 5465,2135 5305,2415 5345,2415 5385,2415 5425,2415 5465,2415 5305,2455 5345,2455 5385,2455 5425,2455 5465,2455 5565,2525 5605,2525 5645,2525 5685,2525 5725,2525 5565,2705 5605,2705 5645,2705 5685,2705 5725,2705
SW-2: C89.2 C116.1 D21.2 L11.1 Q7.4 Q8.4 Q9.3 R76.1 R97.1 | length 1567.1
  Top w30: C89.2@4205,825 v1(4265,825) ; v1(4255,475) R76.1@4255,523.5 4305,523.5 4396.5,615 5265,615 v1(5305,655)
  Inner Top w30: v1(4255,475) 4255,765 4265,775 v1(4265,825)
  other v1: 5345,655 5385,655 5425,655 5465,655 5305,695 5345,695 5385,695 5425,695 5465,695 5305,975 5345,975 5385,975 5425,975 5465,975 5305,1015 5345,1015 5385,1015 5425,1015 5465,1015 5565,1085 5605,1085 5645,1085 5685,1085 5725,1085 5565,1265 5605,1265 5645,1265 5685,1265 5725,1265
SYNC: U11.1 U12.8 | length 2397.4
  Top w15: v1(3655,1035) 3845,1035 3861.02,1018.98 U12.8@3861.02,981.14 ; U11.1@4040.16,2721.14 4041.3,2720 v1(4090,2720)
  Inner Bottom w15: v1(3655,1035) 3655,2680 3695,2720 v1(4090,2720)
UVLO: C91.1 R68.1 R80.2 U11.6 U12.6 | length 2825.7
  Top w15: v1(3575,1115) 3845,1115 3912.2,1047.8 U12.6@3912.2,981.14 ; U11.6@3912.2,2721.14 3912.2,2821.57 3911.89,2821.89 3916.5,2826.5 C91.1@3916.5,2875 R80.2@3916.5,2945 v1(3916.5,2980) R68.1@3916.5,3015
  Inner Bottom w15: v1(3575,1115) 3575,2795 3760,2980 v1(3916.5,2980)
VCC1: C86.1 D14.2 R67.1 U11.17 | length 1111.3
  Top w15: v1@3495,2226.5 R67.1@3495,2275 ; U11.17@3963.07,2498.23 3963.07,2436.93 4015,2385 C86.1@4015,2342.09 4067.09,2342.09 4075.12,2350.12 D14.2@4115,2350.12 4115.12,2350 v1(4170,2350)
  Inner Top w15: v1(3495,2225) 3620,2350 v1(4170,2350)
VCC2: C87.1 D15.2 R70.1 U12.10 U12.17 | length 1677.7
  Top w15: v1(3635,475) R70.1@3635,523.5 ; v1(3760,980) 3808.7,980 U12.10@3809.84,981.14 ; U12.17@3963.39,748.86 3963.39,684.27 4015,632.65 C87.1@4015,592.09 4071.59,592.09 4079.62,600.12 D15.2@4115,600.12 4115.12,600 v1(4175,600)
  Inner Top w15: v1(3635,475) 3760,600 v1(4175,600)
  Inner Bottom w15: v1(3760,980) 3760,855 4015,600 v1(4175,600)
VIN: C97.1 C98.1 C101.1 C104.1 C105.1 C117.1 C118.1 C121.1 J19.1 J19.2 R68.2 R69.2 R71.2 R88.1 R89.1 R91.2 R98.1 R100.2 | length 5056
  Top w15: v1(3795,3015) R68.2@3853.5,3015 R69.2@3853.5,3085 ; R71.2@3835,1226.5 v1(3835,1285) ; R100.2@4256.5,1105 v1(4315,1105) 4315,1145 4755,1585 v1(5895,1585) ; R91.2@4256.5,2855 v1(4315,2855) 4345,2855 4511.83,3021.83 5891.83,3021.83 v1(5895,3025)
  Inner Top w15: v1(3795,3015) 3955,2855 v1(4315,2855) ; v1(3835,1285) 4015,1105 v1(4315,1105)
  Bottom w20: R89.1@7475,2440 C104.1@7633.5,2440
  other v1: 6185,1285 6225,1285 6265,1285 6385,1285 6425,1285 6465,1285 7105,1285 7145,1285 7185,1285 7305,1285 7345,1285 7385,1285 6185,1325 6225,1325 6265,1325 6385,1325 6425,1325 6465,1325 7105,1325 7145,1325 7185,1325 7305,1325 7345,1325 7385,1325 6745,1355 6785,1355 6825,1355 6185,1365 6225,1365 6265,1365 6385,1365 6425,1365 6465,1365 7105,1365 7145,1365 7185,1365 7305,1365 7345,1365 7385,1365 6185,1405 6225,1405 6265,1405 6385,1405 6425,1405 6465,1405 7105,1405 7145,1405 7185,1405 7305,1405 7345,1405 7385,1405 6185,1445 6225,1445 6265,1445 6385,1445 6425,1445 6465,1445 7105,1445 7145,1445 7185,1445 7305,1445 7345,1445 7385,1445 5895,1550 5930,1550 5965,1550 6000,1550 6035,1550 5930,1585 5965,1585 6000,1585 6035,1585 7005,1640 7045,1640 7100,1640 7140,1640 7636.5,1640 7676.5,1640 7731.5,1640 7771.5,1640 7005,1680 7045,1680 7100,1680 7140,1680 7636.5,1680 7676.5,1680 7730,1680 7770,1680 7100,1720 7140,1720 7636.5,1720 7676.5,1720 7100,1760 7140,1760 7635,1760 7675,1760 7098.5,1800 7138.5,1800 7635,1800 7675,1800 7005,1840 7045,1840 7098.5,1840 7138.5,1840 7635,1840 7675,1840 7730,1840 7770,1840 7003.5,1880 7043.5,1880 7098.5,1880 7138.5,1880 7635,1880 7675,1880 7730,1880 7770,1880 7575,2440 7545,2510 7545,2550 7545,2590 6185,2725 6225,2725 6265,2725 6385,2725 6425,2725 6465,2725 7105,2725 7145,2725 7185,2725 7305,2725 7345,2725 7385,2725 6185,2765 6225,2765 6265,2765 6385,2765 6425,2765 6465,2765 7105,2765 7145,2765 7185,2765 7305,2765 7345,2765 7385,2765 6745,2795 6785,2795 6825,2795 6185,2805 6225,2805 6265,2805 6385,2805 6425,2805 6465,2805 7105,2805 7145,2805 7185,2805 7305,2805 7345,2805 7385,2805 6185,2845 6225,2845 6265,2845 6385,2845 6425,2845 6465,2845 7105,2845 7145,2845 7185,2845 7305,2845 7345,2845 7385,2845 6185,2885 6225,2885 6265,2885 6385,2885 6425,2885 6465,2885 7105,2885 7145,2885 7185,2885 7305,2885 7345,2885 7385,2885 5895,2990 5930,2990 5965,2990 6000,2990 6035,2990 5930,3025 5965,3025 6000,3025 6035,3025
pads on no net: D1.MH1 D1.MH2 D2.MH1 D2.MH2 D20.2 FID1.1 FID2.1 FID3.1 FID4.1 J5_1.M1 J5_1.M2 J5_1.M3 J5_2.M1 J5_2.M2 J5_2.M3 J8_1.M1 J8_1.M2 J8_1.M3 J8_2.M1 J8_2.M2 J8_2.M3 L5_1.3 L5_2.3 L6_1.3 L6_2.3 L7_1.3 L7_2.3 L8_1.3 L8_2.3 L9.3 L11.3 S1.MH1 S1.MH2 U1.1 U4.3 U4.6 U4.7 U12.1

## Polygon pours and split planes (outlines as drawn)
GND on Top "Top-No Net 7" (solid, remove dead copper, pour order 514): 25,8215 25,5845 1860,5845 1860,6435 2477.5,6435 2477.5,7610 1860,7610 1860,8215
GND on Top "Top-No Net 5" (solid, pour order 489): 1580,5845 1580,6205 2830,6205 2830,5845
GND on Top "Top-No Net 5" (solid, pour order 491): 1580,7845 1580,8215 2830,8215 2830,7845
NetC65_2_1 on Top "Top-No Net 1" (solid, pour order 453): 2555,7425 2555,7145 2635,7145 2635,7425
NetC55_2_2 on Top "Top-No Net 1" (solid, pour order 452): 2555,6905 2555,6625 2635,6625 2635,6905
NetC55_2_2 on Top "Top-No Net 6" (solid, pour order 478): 2625,6905 2660,6905 3180,6385 3180,5845 2855,5845 2855,6405 2625,6635
NetC65_2_1 on Top "Top-No Net 6" (solid, pour order 481): 2625,7145 2660,7145 3180,7665 3180,8215 2855,8215 2855,7645 2625,7415
NetC54_2_2 on Top "Top-No Net 4" (solid, pour order 470): 2630,6955 2640,6955 2660,6955 3190,6425 3230,6425 3230,7005 2660,7005 2650,7015 2630,7015
NetC64_2_1 on Top "Top-No Net 4" (solid, pour order 472): 2630,7095 2640,7095 2660,7095 3190,7625 3230,7625 3230,7045 2660,7045 2650,7035 2630,7035
NetC54_2_2 on Top "Top-No Net" (solid, remove dead copper, pour order 440): 2565,7015 2555,7005 2555,6965 2565,6955 2635,6955 2635,7015
NetC64_2_1 on Top "Top-No Net" (solid, remove dead copper, pour order 438): 2565,7095 2555,7085 2555,7045 2565,7035 2635,7035 2635,7095
NetC54_2_2 on Top "Top-No Net 3" (solid, remove dead copper, pour order 505): 3225,6425 5575,6425 5575,7005 3225,7005
NetC64_2_1 on Top "Top-No Net 3" (solid, remove dead copper, pour order 506): 3225,7045 5575,7045 5575,7625 3225,7625
NetC65_2_1 on Top "Top-No Net 2" (solid, remove dead copper, pour order 487): 3895,7665 3175,7665 3175,8215 3895,8215
NetC55_2_2 on Top "Top-No Net 2" (solid, remove dead copper, pour order 485): 3895,5845 3175,5845 3175,6385 3895,6385
NetC41_2_1 on Top "Bottom-No Net 1" (solid, remove dead copper, pour order 510): 7825,5845 3935,5845 3935,6385 7825,6385
NetC61_2_1 on Top "Bottom-No Net" (solid, remove dead copper, pour order 501): 7825,6425 7825,7005 5615,7005 5615,6425
NetC74_2_1 on Top "Bottom-No Net 1" (solid, remove dead copper, pour order 512): 7825,8215 3935,8215 3935,7665 7825,7665
NetC68_2_1 on Top "Bottom-No Net" (solid, remove dead copper, pour order 502): 7825,7045 7825,7625 5615,7625 5615,7045
PVDD on Top "Inner Top-No Net 16" (solid, remove dead copper, pour order 466): 2830,6245 2830,6395 1900,6395 1900,6245
PVDD on Top "Inner Top-No Net 16" (solid, remove dead copper, pour order 463): 2830,7650 2830,7800 1900,7800 1900,7650
PVDD on Top "Inner Top-No Net 16" (solid, remove dead copper, pour order 464): 2830,5130 2830,5280 1900,5280 1900,5130
PVDD on Top "Inner Top-No Net 16" (solid, remove dead copper, pour order 465): 2830,3725 2830,3875 1900,3875 1900,3725
GND on Top "Top-No Net 33" (solid, pour order 516): 2545,345 2545,3175 25,3175 25,345
NetC10_2 on Top "Top-No Net 32" (solid, pour order 441): 2060,655 2060,540 1990,540 1990,580 2030,580 2030,655
-12V on Top "Top-No Net 29" (solid, pour order 455): 2285,1040 2135,1040 2115,1060 2115,1255 2205,1255 2205,1120 2225,1100 2285,1100
NetC10_2 on Top "Top-No Net 28" (solid, pour order 456): 2220,735 2220,955.08 2234.92,970 2280,970 2285,970 2285,1030 2135,1030 2135,915 2095,875 2030,875 2030,775 2095,775 2135,735
PVDD on Top "Top-No Net 25" (solid, pour order 449): 2030,740 2105,740 2110,740 2130,720 2220,720 2220,570 2120,570 2120,661.54 2106.54,675 2030,675
NetC9_1 on Top "Top-No Net 27" (solid, pour order 457): 2020,675 1885,675 1885,840 1885,1115 1975,1115 1975,920 2020,875
NetC9_2 on Top "Top-No Net 26" (solid, pour order 443): 1885,655 2020,655 2020,585 1885,585
GND on Top "Top-No Net 31" (solid, pour order 436): 1380,655 1350,655 1350,560 1380,560
GND on Top "Top-No Net 30" (solid, pour order 444): 1445,875 1350,875 1350,775 1445,775
+12V on Top "Top-No Net 29" (solid, pour order 454): 1605,1045 1455,1045 1435,1065 1435,1260 1525,1260 1525,1125 1545,1105 1605,1105
NetC5_1 on Top "Top-No Net 28" (solid, pour order 458): 1540,735 1540,955.08 1554.92,970 1600,970 1605,970 1605,1030 1445,1030 1425,1050 1425,1180 1310,1180 1310,885 1455,885 1455,735
NetC3_1 on Top "Top-No Net 27" (solid, pour order 459): 1340,675 1205,675 1205,840 1125,920 1125,1180 1295,1180 1295,885 1340,840
NetC3_2 on Top "Top-No Net 26" (solid, pour order 442): 1205,655 1340,655 1340,585 1205,585
PVDD on Top "Top-No Net 25" (solid, pour order 448): 1350,740 1425,740 1430,740 1450,720 1540,720 1540,570 1440,570 1440,661.54 1426.54,675 1350,675
+3V3 on Top "Top-No Net 24" (solid, pour order 446): 585,585 525,585 525,760 605,760 605,670 585,650
NetC16_1 on Top "Top-No Net 23" (solid, pour order 445): 780,475 645,475 645,390 780,390
+12V on Top "Top-No Net 23" (solid, pour order 447): 610,475 450,475 450,390 610,390
PVDD on Top "Top-No Net 22" (solid, pour order 513): 2585,3175 3345,3175 3345,345 2585,345
PVDD on Top "Top-No Net 22" (solid, pour order 498): 4345,2095 4345,1375 2735,1375 2735,2095
PVDD on Top "Top-No Net 21" (solid, pour order 461): 5125,1735 5125,1605 4325,1605 4325,1735
NetC95_2 on Top "Top-No Net 20" (solid, pour order 467): 4385,1775 5125,1775 5125,2015 4385,2015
